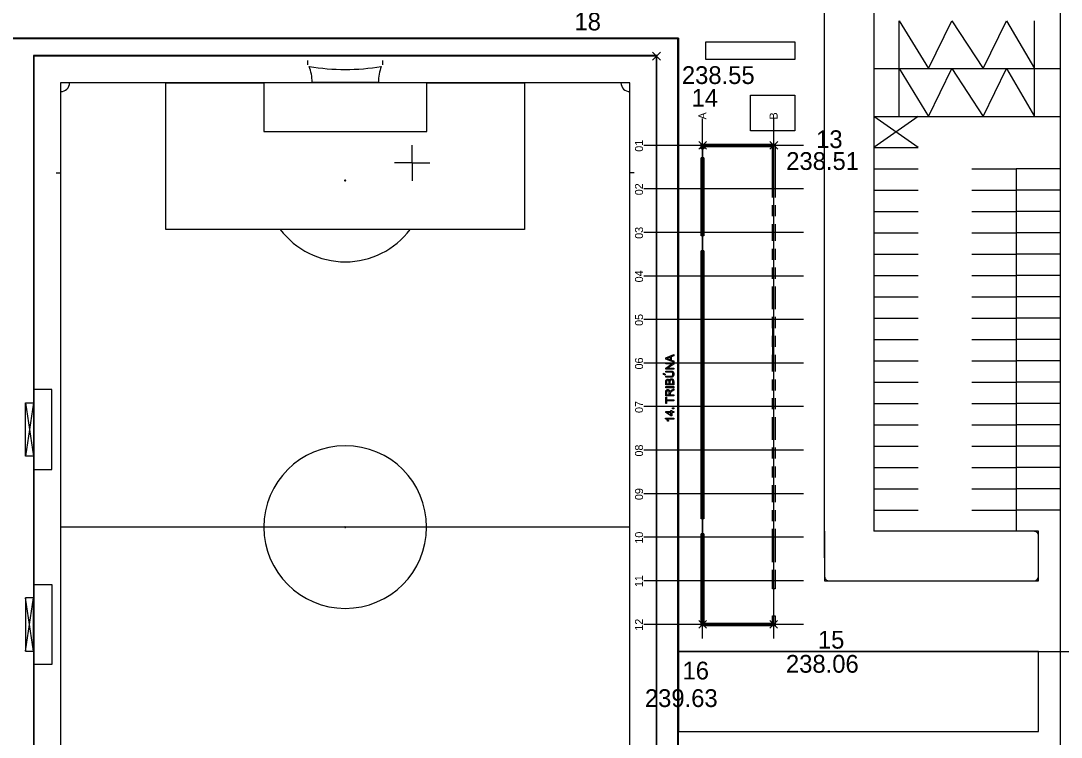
# Model space of a CAD drawing. Extents: x -264165 to -263575, y -1242333 to -1242036.
# Drawn here: x -264044 to -263927, y -1242264.6 to -1242184 of the extents above; entities that cross this region are included whole.
import ezdxf

# ---------------------------------------------------------------- set-up
doc = ezdxf.new("R2010")
doc.units = 0
for name, color, linetype in [('KFA_BODY_VYTYCOVAK', 7, 'Continuous'), ('KFA_HEKT_SIET_1-1000', 7, 'Continuous'), ('KFA_HESCON_OSI_STAVBY', 7, 'Continuous'), ('KFA_SITUACIA_DRS_VYTYCOVAK_SEDA', 7, 'Continuous')]:
    doc.layers.add(name, color=color, linetype=linetype)

msp = doc.modelspace()

# ---------------------------------------------------------------- linework, layer by layer
at = {"layer": 'KFA_BODY_VYTYCOVAK'}
for p, q in [((-263972.97, -1242188.42), (-263972.09, -1242187.54)), ((-263972.09, -1242188.42), (-263972.97, -1242187.54)), ((-263967.78, -1242198.47), (-263966.9, -1242197.59)), ((-263966.9, -1242198.47), (-263967.78, -1242197.59)), ((-263959.77, -1242198.46), (-263958.89, -1242197.58)), ((-263958.89, -1242198.46), (-263959.77, -1242197.58)), ((-263967.77, -1242252.37), (-263966.89, -1242251.49)), ((-263966.89, -1242252.37), (-263967.77, -1242251.49)), ((-263959.79, -1242252.36), (-263958.91, -1242251.48)), ((-263958.91, -1242252.36), (-263959.79, -1242251.48))]:
    msp.add_line(p, q, dxfattribs=at)
at = {"layer": 'KFA_HEKT_SIET_1-1000'}
for q in [(-264000, -1242198), (-264002, -1242200), (-263998, -1242200), (-264000, -1242202)]:
    msp.add_line((-264000, -1242200), q, dxfattribs=at)
at = {"layer": 'KFA_HESCON_OSI_STAVBY'}
for p, q in [((-263967.34, -1242253.53), (-263967.34, -1242195)), ((-263959.34, -1242253.53), (-263959.34, -1242195)), ((-263955.98, -1242198.03), (-263973.94, -1242198.03)), ((-263955.98, -1242202.93), (-263973.94, -1242202.93)), ((-263955.98, -1242207.83), (-263973.94, -1242207.83)), ((-263955.98, -1242212.73), (-263973.94, -1242212.73)), ((-263955.98, -1242217.63), (-263973.94, -1242217.63)), ((-263955.98, -1242222.53), (-263973.94, -1242222.53)), ((-263955.98, -1242227.43), (-263973.94, -1242227.43)), ((-263955.98, -1242232.33), (-263973.94, -1242232.33)), ((-263955.98, -1242237.23), (-263973.94, -1242237.23)), ((-263955.98, -1242242.13), (-263973.94, -1242242.13)), ((-263955.98, -1242247.03), (-263973.94, -1242247.03)), ((-263955.98, -1242251.93), (-263973.94, -1242251.93))]:
    msp.add_line(p, q, dxfattribs=at)
at = {"layer": 'KFA_SITUACIA_DRS_VYTYCOVAK_SEDA'}
for p, q in [((-263948.09, -1242087.31), (-263948.09, -1242241.46)), ((-263927.09, -1242254.98), (-263927.09, -1242087.31)), ((-263948.09, -1242087.9), (-263948.09, -1242241.46)), ((-263953.62, -1242241.46), (-263953.62, -1242093.31)), ((-263953.62, -1242244.46), (-263953.62, -1242093.31)), ((-263945.26, -1242189.38), (-263945.26, -1242184.01)), ((-263945.26, -1242184.01), (-263941.94, -1242189.38)), ((-263941.94, -1242189.38), (-263939.33, -1242184.01)), ((-263939.33, -1242184.01), (-263935.8, -1242189.38)), ((-263935.8, -1242189.38), (-263933.19, -1242184.01)), ((-263933.19, -1242184.01), (-263930.03, -1242189.38)), ((-263930.03, -1242189.38), (-263930.03, -1242184.01)), ((-264120.57, -1242185.98), (-263970.07, -1242185.98)), ((-263970.07, -1242185.98), (-264120.07, -1242185.98)), ((-263970.12, -1242186.03), (-264120.02, -1242186.03)), ((-263970.12, -1242296.38), (-263970.12, -1242186.03)), ((-263970.07, -1242185.98), (-263970.07, -1242254.98)), ((-263970.07, -1242296.43), (-263970.07, -1242185.98)), ((-263966.97, -1242186.38), (-263956.97, -1242186.38)), ((-263966.97, -1242188.38), (-263966.97, -1242186.38)), ((-263966.97, -1242186.38), (-263956.97, -1242186.38)), ((-263966.97, -1242188.38), (-263966.97, -1242186.38)), ((-263956.97, -1242186.38), (-263956.97, -1242188.38)), ((-263956.97, -1242186.38), (-263956.97, -1242188.38)), ((-263972.47, -1242187.93), (-264042.57, -1242187.93)), ((-264042.57, -1242187.93), (-264042.57, -1242294.03)), ((-263972.47, -1242187.93), (-264042.57, -1242187.93)), ((-264042.57, -1242187.93), (-264042.57, -1242294.03)), ((-263972.52, -1242187.98), (-264042.52, -1242187.98)), ((-264042.52, -1242187.98), (-264042.52, -1242293.98)), ((-263972.52, -1242293.98), (-263972.52, -1242187.98)), ((-263972.47, -1242294.03), (-263972.47, -1242187.93)), ((-263972.47, -1242294.03), (-263972.47, -1242187.93)), ((-264011.74, -1242188.98), (-264011.74, -1242188.46)), ((-264003.3, -1242188.98), (-264003.3, -1242188.46)), ((-263956.97, -1242188.38), (-263966.97, -1242188.38)), ((-263956.97, -1242188.38), (-263966.97, -1242188.38)), ((-263948.09, -1242189.38), (-263927.09, -1242189.38)), ((-263945.26, -1242194.76), (-263945.26, -1242189.38)), ((-263945.26, -1242189.38), (-263941.94, -1242194.76)), ((-263941.94, -1242194.76), (-263939.33, -1242189.38)), ((-263939.33, -1242189.38), (-263935.8, -1242194.76)), ((-263935.8, -1242194.76), (-263933.19, -1242189.38)), ((-263933.19, -1242189.38), (-263930.03, -1242194.76)), ((-263930.03, -1242194.76), (-263930.03, -1242189.38)), ((-263975.52, -1242190.98), (-264039.52, -1242190.98)), ((-264039.52, -1242190.98), (-264039.52, -1242290.98)), ((-264027.68, -1242207.48), (-264027.68, -1242190.98)), ((-264027.68, -1242190.98), (-264016.68, -1242190.98)), ((-264016.68, -1242190.98), (-264016.68, -1242196.48)), ((-264011.24, -1242190.92), (-264003.8, -1242190.92)), ((-263975.52, -1242190.98), (-264001.15, -1242190.98)), ((-263975.52, -1242190.98), (-264001.15, -1242190.98)), ((-263998.36, -1242196.48), (-263998.36, -1242190.98)), ((-263998.36, -1242190.98), (-263987.36, -1242190.98)), ((-263998.36, -1242196.48), (-263998.36, -1242190.98)), ((-263998.36, -1242190.98), (-263987.36, -1242190.98)), ((-263987.36, -1242190.98), (-263987.36, -1242207.48)), ((-263987.36, -1242190.98), (-263987.36, -1242207.48)), ((-263975.52, -1242290.98), (-263975.52, -1242190.98)), ((-263975.52, -1242290.98), (-263975.52, -1242190.98)), ((-263975.52, -1242290.98), (-263975.52, -1242190.98)), ((-263961.97, -1242192.38), (-263956.97, -1242192.38)), ((-263961.97, -1242196.38), (-263961.97, -1242192.38)), ((-263961.97, -1242192.38), (-263956.97, -1242192.38)), ((-263961.97, -1242196.38), (-263961.97, -1242192.38)), ((-263956.97, -1242192.38), (-263956.97, -1242196.38)), ((-263956.97, -1242192.38), (-263956.97, -1242196.38)), ((-263948.09, -1242194.76), (-263927.09, -1242194.76)), ((-263943.09, -1242194.76), (-263948.09, -1242198.26)), ((-263943.09, -1242198.26), (-263948.09, -1242194.76)), ((-264016.68, -1242196.48), (-263998.36, -1242196.48)), ((-264001.15, -1242196.48), (-263998.36, -1242196.48)), ((-263956.97, -1242196.38), (-263961.97, -1242196.38)), ((-263956.97, -1242196.38), (-263961.97, -1242196.38)), ((-263967.49, -1242198.43), (-263967.49, -1242197.88)), ((-263967.49, -1242197.88), (-263959.19, -1242197.88)), ((-263967.19, -1242198.43), (-263967.49, -1242198.43)), ((-263959.34, -1242198.03), (-263967.34, -1242198.03)), ((-263967.34, -1242198.03), (-263967.34, -1242242.23)), ((-263959.49, -1242198.18), (-263967.19, -1242198.18)), ((-263967.19, -1242198.18), (-263967.19, -1242198.43)), ((-263959.49, -1242203.88), (-263959.49, -1242198.18)), ((-263959.34, -1242251.93), (-263959.34, -1242198.03)), ((-263959.19, -1242197.88), (-263959.19, -1242203.88)), ((-263948.09, -1242198.26), (-263943.09, -1242198.26)), ((-263967.49, -1242208.22), (-263967.49, -1242199.43)), ((-263967.19, -1242199.43), (-263967.49, -1242199.43)), ((-263967.19, -1242199.43), (-263967.19, -1242208.22)), ((-263967.19, -1242200.03), (-263967.19, -1242201.93)), ((-263948.09, -1242200.66), (-263943.09, -1242200.66)), ((-263937.09, -1242200.66), (-263932.09, -1242200.66)), ((-263932.09, -1242200.66), (-263932.09, -1242241.46)), ((-263927.09, -1242200.66), (-263932.09, -1242200.66)), ((-264040.02, -1242201.13), (-264039.52, -1242201.13)), ((-263975.02, -1242201.13), (-263975.52, -1242201.13)), ((-263948.09, -1242203.06), (-263943.09, -1242203.06)), ((-263937.09, -1242203.06), (-263932.09, -1242203.06)), ((-263927.09, -1242203.06), (-263932.09, -1242203.06)), ((-263959.49, -1242206.01), (-263959.49, -1242204.76)), ((-263959.19, -1242204.76), (-263959.19, -1242206.01)), ((-263948.09, -1242205.46), (-263943.09, -1242205.46)), ((-263937.09, -1242205.46), (-263932.09, -1242205.46)), ((-263927.09, -1242205.46), (-263932.09, -1242205.46)), ((-263987.36, -1242207.48), (-264027.68, -1242207.48)), ((-263987.36, -1242207.48), (-264001.15, -1242207.48)), ((-263959.49, -1242208.78), (-263959.49, -1242206.88)), ((-263959.19, -1242206.88), (-263959.19, -1242208.78)), ((-263948.09, -1242207.86), (-263943.09, -1242207.86)), ((-263937.09, -1242207.86), (-263932.09, -1242207.86)), ((-263927.09, -1242207.86), (-263932.09, -1242207.86)), ((-263967.19, -1242208.22), (-263967.49, -1242208.22)), ((-263967.19, -1242209.89), (-263967.49, -1242209.89)), ((-263967.49, -1242240.07), (-263967.49, -1242209.89)), ((-263967.19, -1242209.89), (-263967.19, -1242240.07)), ((-263959.49, -1242210.91), (-263959.49, -1242209.66)), ((-263959.19, -1242209.66), (-263959.19, -1242210.91)), ((-263948.09, -1242210.26), (-263943.09, -1242210.26)), ((-263937.09, -1242210.26), (-263932.09, -1242210.26)), ((-263927.09, -1242210.26), (-263932.09, -1242210.26)), ((-263959.49, -1242213.03), (-263959.49, -1242211.78)), ((-263959.19, -1242211.78), (-263959.19, -1242213.03)), ((-263948.09, -1242212.66), (-263943.09, -1242212.66)), ((-263937.09, -1242212.66), (-263932.09, -1242212.66)), ((-263927.09, -1242212.66), (-263932.09, -1242212.66)), ((-263959.49, -1242216.46), (-263959.49, -1242213.91)), ((-263959.19, -1242213.91), (-263959.19, -1242216.46)), ((-263948.09, -1242215.06), (-263943.09, -1242215.06)), ((-263937.09, -1242215.06), (-263932.09, -1242215.06)), ((-263927.09, -1242215.06), (-263932.09, -1242215.06)), ((-263959.49, -1242218.58), (-263959.49, -1242217.33)), ((-263959.49, -1242217.71), (-263959.49, -1242222.46)), ((-263959.19, -1242217.33), (-263959.19, -1242218.58)), ((-263948.09, -1242217.46), (-263943.09, -1242217.46)), ((-263937.09, -1242217.46), (-263932.09, -1242217.46)), ((-263927.09, -1242217.46), (-263932.09, -1242217.46)), ((-263959.49, -1242220.71), (-263959.49, -1242219.46)), ((-263959.19, -1242219.46), (-263959.19, -1242220.71)), ((-263948.09, -1242219.86), (-263943.09, -1242219.86)), ((-263937.09, -1242219.86), (-263932.09, -1242219.86)), ((-263927.09, -1242219.86), (-263932.09, -1242219.86)), ((-263959.49, -1242223.48), (-263959.49, -1242221.58)), ((-263959.19, -1242221.58), (-263959.19, -1242223.48)), ((-263948.09, -1242222.26), (-263943.09, -1242222.26)), ((-263937.09, -1242222.26), (-263932.09, -1242222.26)), ((-263927.09, -1242222.26), (-263932.09, -1242222.26)), ((-263959.49, -1242225.61), (-263959.49, -1242224.36)), ((-263959.19, -1242224.36), (-263959.19, -1242225.61)), ((-263948.09, -1242224.66), (-263943.09, -1242224.66)), ((-263937.09, -1242224.66), (-263932.09, -1242224.66)), ((-263927.09, -1242224.66), (-263932.09, -1242224.66)), ((-264040.52, -1242225.51), (-264042.52, -1242225.51)), ((-264040.52, -1242234.51), (-264040.52, -1242225.51)), ((-263959.49, -1242227.73), (-263959.49, -1242226.48)), ((-263959.19, -1242226.48), (-263959.19, -1242227.73)), ((-264043.47, -1242227.01), (-264042.57, -1242233.01)), ((-264042.57, -1242227.01), (-264043.47, -1242233.01)), ((-264043.47, -1242233.01), (-264043.47, -1242227.01)), ((-264043.47, -1242227.01), (-264042.57, -1242227.01)), ((-264042.57, -1242227.01), (-264042.57, -1242233.01)), ((-263948.09, -1242227.06), (-263943.09, -1242227.06)), ((-263937.09, -1242227.06), (-263932.09, -1242227.06)), ((-263927.09, -1242227.06), (-263932.09, -1242227.06)), ((-263959.49, -1242231.16), (-263959.49, -1242228.61)), ((-263959.19, -1242228.61), (-263959.19, -1242231.16)), ((-263948.09, -1242229.46), (-263943.09, -1242229.46)), ((-263937.09, -1242229.46), (-263932.09, -1242229.46)), ((-263927.09, -1242229.46), (-263932.09, -1242229.46)), ((-263959.49, -1242233.28), (-263959.49, -1242232.03)), ((-263959.19, -1242232.03), (-263959.19, -1242233.28)), ((-263948.09, -1242231.86), (-263943.09, -1242231.86)), ((-263937.09, -1242231.86), (-263932.09, -1242231.86)), ((-263927.09, -1242231.86), (-263932.09, -1242231.86)), ((-264042.57, -1242233.01), (-264043.47, -1242233.01)), ((-264042.52, -1242234.51), (-264040.52, -1242234.51)), ((-263959.49, -1242235.41), (-263959.49, -1242234.16)), ((-263959.19, -1242234.16), (-263959.19, -1242235.41)), ((-263948.09, -1242234.26), (-263943.09, -1242234.26)), ((-263937.09, -1242234.26), (-263932.09, -1242234.26)), ((-263927.09, -1242234.26), (-263932.09, -1242234.26)), ((-263959.49, -1242238.18), (-263959.49, -1242236.28)), ((-263959.19, -1242236.28), (-263959.19, -1242238.18)), ((-263948.09, -1242236.66), (-263943.09, -1242236.66)), ((-263937.09, -1242236.66), (-263932.09, -1242236.66)), ((-263927.09, -1242236.66), (-263932.09, -1242236.66)), ((-263959.49, -1242240.31), (-263959.49, -1242239.06)), ((-263959.19, -1242239.06), (-263959.19, -1242240.31)), ((-263948.09, -1242239.06), (-263943.09, -1242239.06)), ((-263937.09, -1242239.06), (-263932.09, -1242239.06)), ((-263927.09, -1242239.06), (-263932.09, -1242239.06)), ((-263967.19, -1242240.07), (-263967.49, -1242240.07)), ((-263975.52, -1242240.98), (-264039.52, -1242240.98)), ((-263975.52, -1242240.98), (-264001.15, -1242240.98)), ((-263975.52, -1242240.98), (-264001.15, -1242240.98)), ((-263967.19, -1242241.74), (-263967.49, -1242241.74)), ((-263967.49, -1242252.08), (-263967.49, -1242241.74)), ((-263967.19, -1242241.74), (-263967.19, -1242251.78)), ((-263959.49, -1242244.93), (-263959.49, -1242241.18)), ((-263959.19, -1242241.18), (-263959.19, -1242244.93)), ((-263953.62, -1242241.46), (-263953.62, -1242247.03)), ((-263929.58, -1242241.46), (-263948.09, -1242241.46)), ((-263930.08, -1242241.46), (-263948.09, -1242241.46)), ((-263929.58, -1242247.03), (-263929.58, -1242241.46)), ((-263967.34, -1242242.23), (-263967.34, -1242251.93)), ((-263929.58, -1242246.53), (-263929.58, -1242241.96)), ((-263953.62, -1242244.46), (-263953.62, -1242246.53)), ((-263959.49, -1242247.93), (-263959.49, -1242245.81)), ((-263959.19, -1242245.81), (-263959.19, -1242247.93)), ((-264042.52, -1242247.46), (-264040.52, -1242247.46)), ((-264040.52, -1242247.46), (-264040.52, -1242256.46)), ((-263953.62, -1242247.03), (-263929.58, -1242247.03)), ((-263953.12, -1242247.03), (-263930.08, -1242247.03)), ((-263959.19, -1242247.93), (-263959.49, -1242247.93)), ((-263959.19, -1242247.81), (-263959.19, -1242247.93)), ((-264043.47, -1242254.96), (-264042.57, -1242248.96)), ((-264042.57, -1242254.96), (-264043.47, -1242248.96)), ((-264043.47, -1242248.96), (-264043.47, -1242254.96)), ((-264042.57, -1242248.96), (-264043.47, -1242248.96)), ((-264042.57, -1242254.96), (-264042.57, -1242248.96)), ((-263959.49, -1242251.78), (-263959.49, -1242250.96)), ((-263959.49, -1242250.96), (-263959.19, -1242250.96)), ((-263959.19, -1242250.96), (-263959.19, -1242252.08)), ((-263959.19, -1242252.08), (-263967.49, -1242252.08)), ((-263967.34, -1242251.93), (-263959.34, -1242251.93)), ((-263967.19, -1242251.78), (-263959.49, -1242251.78)), ((-264043.47, -1242254.96), (-264042.57, -1242254.96)), ((-263929.58, -1242254.98), (-263970.08, -1242254.98)), ((-263970.08, -1242254.98), (-263970.08, -1242263.98)), ((-263970.07, -1242254.98), (-263802.07, -1242254.99)), ((-263929.58, -1242254.98), (-263970.07, -1242254.98)), ((-263970.07, -1242254.98), (-263970.07, -1242263.98)), ((-263929.58, -1242254.98), (-263920.08, -1242254.98)), ((-263929.58, -1242263.98), (-263929.58, -1242254.98)), ((-263929.58, -1242263.98), (-263929.58, -1242254.98)), ((-263927.09, -1242267.98), (-263927.09, -1242254.98)), ((-264040.52, -1242256.46), (-264042.52, -1242256.46)), ((-263970.08, -1242263.98), (-263929.58, -1242263.98)), ((-263970.07, -1242263.98), (-263929.58, -1242263.98))]:
    msp.add_line(p, q, dxfattribs=at)
for points in [[(-263970.59, -1242222.41), (-263971.49, -1242222.07), (-263971.49, -1242221.94), (-263970.59, -1242221.57), (-263970.59, -1242221.71), (-263970.86, -1242221.81), (-263970.86, -1242222.19), (-263970.59, -1242222.29), (-263970.59, -1242222.41)], [(-263970.96, -1242222.15), (-263970.96, -1242221.85), (-263971.21, -1242221.94)], [(-263970.59, -1242223.23), (-263971.49, -1242223.23), (-263971.49, -1242223.1), (-263970.79, -1242222.63), (-263971.49, -1242222.63), (-263971.49, -1242222.52), (-263970.59, -1242222.52), (-263970.59, -1242222.64), (-263971.3, -1242223.11), (-263970.59, -1242223.11), (-263970.59, -1242223.23)], [(-263971.23, -1242222.06), (-263970.96, -1242222.15)], [(-263971.55, -1242223.88), (-263971.72, -1242223.8), (-263971.72, -1242223.65), (-263971.55, -1242223.78), (-263971.55, -1242223.88)], [(-263971.49, -1242223.54), (-263971.49, -1242223.42), (-263970.97, -1242223.42)], [(-263970.97, -1242223.54), (-263971.49, -1242223.54)], [(-263970.97, -1242224.13), (-263971.49, -1242224.13), (-263971.49, -1242224.01), (-263970.97, -1242224.01)], [(-263970.59, -1242224.98), (-263971.49, -1242224.98), (-263971.49, -1242224.64)], [(-263970.59, -1242225.3), (-263971.49, -1242225.3), (-263971.49, -1242225.18), (-263970.59, -1242225.18), (-263970.59, -1242225.3)], [(-263971.39, -1242224.68), (-263971.39, -1242224.86), (-263971.11, -1242224.86)], [(-263971.11, -1242224.86), (-263971.11, -1242224.66)], [(-263971.01, -1242224.65), (-263971.01, -1242224.86), (-263970.7, -1242224.86)], [(-263970.84, -1242225.59), (-263970.59, -1242225.43), (-263970.59, -1242225.58), (-263970.78, -1242225.7)], [(-263970.7, -1242224.86), (-263970.7, -1242224.63)], [(-263970.59, -1242224.63), (-263970.59, -1242224.98)], [(-263970.59, -1242226.23), (-263971.49, -1242226.23), (-263971.49, -1242225.83)], [(-263970.59, -1242226.77), (-263971.39, -1242226.77), (-263971.39, -1242227.06), (-263971.49, -1242227.06), (-263971.49, -1242226.35), (-263971.39, -1242226.35), (-263971.39, -1242226.65), (-263970.59, -1242226.65), (-263970.59, -1242226.77)], [(-263971.39, -1242225.82), (-263971.39, -1242226.11), (-263971.1, -1242226.11)], [(-263971.1, -1242226.11), (-263971.1, -1242225.85)], [(-263970.99, -1242225.97), (-263970.99, -1242226.11), (-263970.59, -1242226.11), (-263970.59, -1242226.23)], [(-263970.59, -1242227.68), (-263970.72, -1242227.68), (-263970.72, -1242227.55), (-263970.59, -1242227.55), (-263970.59, -1242227.68)], [(-263971.5, -1242228.79), (-263971.5, -1242228.72), (-263970.59, -1242228.72)], [(-263970.59, -1242228.09), (-263970.81, -1242228.09), (-263970.81, -1242228.48), (-263970.91, -1242228.48), (-263971.49, -1242228.07), (-263971.49, -1242227.97), (-263970.91, -1242227.97), (-263970.91, -1242227.85), (-263970.81, -1242227.85), (-263970.81, -1242227.97), (-263970.59, -1242227.97), (-263970.59, -1242228.09)], [(-263970.91, -1242228.09), (-263971.32, -1242228.09), (-263970.91, -1242228.37), (-263970.91, -1242228.09)], [(-263970.59, -1242228.72), (-263970.59, -1242228.83), (-263971.3, -1242228.83)], [(-263971.16, -1242229.05), (-263971.27, -1242229.05)]]:
    msp.add_lwpolyline(points, dxfattribs=at)
msp.add_circle((-264007.52, -1242201.98), 0.06, dxfattribs=at)
for centre, radius, start, end in [((-264016.21, -1242190.94), 4.97, 0.2148, 21.1609), ((-264007.52, -1242164.77), 24.71, 260.5547, 279.4454), ((-263998.83, -1242190.94), 4.97, 158.8391, 179.7852), ((-264039.52, -1242190.98), 1, 270, 360), ((-263975.52, -1242190.98), 1, 180, 270), ((-264007.52, -1242201.98), 0.0303, 90, 270), ((-264007.52, -1242201.98), 0.0303, 270, 90), ((-264007.52, -1242201.98), 9.15, 216.9482, 323.0518), ((-264007.52, -1242240.98), 9.15, 360, 180), ((-264007.52, -1242240.98), 9.15, 180, 360), ((-264007.52, -1242240.98), 0.0605, 90, 270), ((-264007.52, -1242240.98), 0.0605, 270, 90), ((-263930.08, -1242241.96), 0.5, 359.9785, 89.9999), ((-263953.12, -1242246.53), 0.5, 179.9525, 270), ((-263930.08, -1242246.53), 0.5, 270, 359.9785)]:
    msp.add_arc(centre, radius, start, end, dxfattribs=at)
for points in [[(-263971.21, -1242221.94), (-263971.33, -1242221.99), (-263971.4, -1242222.01), (-263971.31, -1242222.02), (-263971.23, -1242222.06)], [(-263971.49, -1242224.64), (-263971.49, -1242224.54), (-263971.47, -1242224.47), (-263971.44, -1242224.41), (-263971.38, -1242224.38), (-263971.32, -1242224.34), (-263971.26, -1242224.34), (-263971.2, -1242224.34), (-263971.15, -1242224.37), (-263971.1, -1242224.4), (-263971.07, -1242224.47), (-263971.05, -1242224.38), (-263970.99, -1242224.34), (-263970.93, -1242224.3), (-263970.85, -1242224.3), (-263970.79, -1242224.3), (-263970.74, -1242224.32), (-263970.68, -1242224.35), (-263970.65, -1242224.39), (-263970.62, -1242224.43), (-263970.61, -1242224.49), (-263970.59, -1242224.55), (-263970.59, -1242224.63)], [(-263970.97, -1242223.42), (-263970.84, -1242223.42), (-263970.76, -1242223.45), (-263970.68, -1242223.48), (-263970.63, -1242223.56), (-263970.58, -1242223.64), (-263970.58, -1242223.77), (-263970.58, -1242223.9), (-263970.62, -1242223.98), (-263970.66, -1242224.06), (-263970.75, -1242224.1), (-263970.83, -1242224.13), (-263970.97, -1242224.13)], [(-263970.97, -1242224.01), (-263970.86, -1242224.01), (-263970.8, -1242223.99), (-263970.75, -1242223.97), (-263970.72, -1242223.91), (-263970.69, -1242223.86), (-263970.69, -1242223.78), (-263970.69, -1242223.65), (-263970.74, -1242223.6), (-263970.8, -1242223.54), (-263970.97, -1242223.54)], [(-263971.11, -1242224.66), (-263971.11, -1242224.58), (-263971.13, -1242224.55), (-263971.14, -1242224.5), (-263971.17, -1242224.48), (-263971.2, -1242224.46), (-263971.25, -1242224.46), (-263971.29, -1242224.46), (-263971.33, -1242224.48), (-263971.36, -1242224.5), (-263971.37, -1242224.54), (-263971.39, -1242224.58), (-263971.39, -1242224.68)], [(-263970.7, -1242224.63), (-263970.7, -1242224.57), (-263970.7, -1242224.55), (-263970.71, -1242224.51), (-263970.73, -1242224.48), (-263970.75, -1242224.45), (-263970.78, -1242224.44), (-263970.81, -1242224.42), (-263970.85, -1242224.42), (-263970.9, -1242224.42), (-263970.94, -1242224.45), (-263970.98, -1242224.47), (-263970.99, -1242224.52), (-263971.01, -1242224.56), (-263971.01, -1242224.65)], [(-263971.49, -1242225.83), (-263971.49, -1242225.71), (-263971.47, -1242225.64), (-263971.44, -1242225.58), (-263971.38, -1242225.54), (-263971.32, -1242225.51), (-263971.25, -1242225.51), (-263971.15, -1242225.51), (-263971.09, -1242225.57), (-263971.02, -1242225.63), (-263971, -1242225.76), (-263970.98, -1242225.71), (-263970.96, -1242225.69), (-263970.91, -1242225.64), (-263970.84, -1242225.59)], [(-263971.1, -1242225.85), (-263971.1, -1242225.77), (-263971.11, -1242225.72), (-263971.13, -1242225.68), (-263971.17, -1242225.65), (-263971.2, -1242225.63), (-263971.25, -1242225.63), (-263971.31, -1242225.63), (-263971.35, -1242225.68), (-263971.39, -1242225.72), (-263971.39, -1242225.82)], [(-263970.78, -1242225.7), (-263970.86, -1242225.75), (-263970.9, -1242225.79), (-263970.95, -1242225.82), (-263970.96, -1242225.85), (-263970.98, -1242225.88), (-263970.99, -1242225.9), (-263970.99, -1242225.92), (-263970.99, -1242225.97)], [(-263971.27, -1242229.05), (-263971.31, -1242228.96), (-263971.38, -1242228.89), (-263971.44, -1242228.82), (-263971.5, -1242228.79)], [(-263971.3, -1242228.83), (-263971.26, -1242228.87), (-263971.22, -1242228.94), (-263971.18, -1242229), (-263971.16, -1242229.05)]]:
    msp.add_open_spline(points, degree=3, dxfattribs=at)

# ---------------------------------------------------------------- texts
at = {"layer": 'KFA_BODY_VYTYCOVAK'}
for s, p in [('18', (-263981.75, -1242185.09)), ('238.55', (-263969.67, -1242191.12)), ('14', (-263968.58, -1242193.68)), ('13', (-263954.58, -1242198.33)), ('238.51', (-263957.94, -1242200.79)), ('15', (-263954.38, -1242254.66)), ('238.06', (-263957.97, -1242257.37)), ('16', (-263969.6, -1242258.13)), ('239.63', (-263973.83, -1242261.23))]:
    msp.add_text(s, height=2, dxfattribs=at).set_placement(p)
at = {"layer": 'KFA_HESCON_OSI_STAVBY'}
for s, p in [('A', (-263966.91, -1242195.11)), ('B', (-263958.91, -1242195.11)), ('01', (-263974.04, -1242198.74)), ('02', (-263974.04, -1242203.64)), ('03', (-263974.04, -1242208.54)), ('04', (-263974.04, -1242213.44)), ('05', (-263974.04, -1242218.34)), ('06', (-263974.04, -1242223.24)), ('07', (-263974.04, -1242228.14)), ('08', (-263974.04, -1242233.04)), ('09', (-263974.04, -1242237.94)), ('10', (-263974.04, -1242242.84)), ('11', (-263974.04, -1242247.74)), ('12', (-263974.04, -1242252.64))]:
    msp.add_text(s, height=0.9, rotation=90, dxfattribs=at).set_placement(p)

doc.saveas('drawing.dxf')
